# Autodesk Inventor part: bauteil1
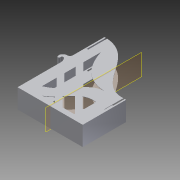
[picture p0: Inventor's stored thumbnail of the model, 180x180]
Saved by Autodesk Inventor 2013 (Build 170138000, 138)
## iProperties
Created: 2012-11
Part Number: bauteil1
Material: Polystyrol
Document SubType Name: Modellieren
Designer: otto
Density: 1.021 g/cm^3
Sheet Metal Width: 0,000 mm
Sheet Metal Length: 0,000 mm
Sheet Metal Area: 0,000 mm^2
Mass: 241.139 g
Surface Area: 2928.45 cm^2
Volume: 236.179 cm^3
Stärke: 3,048 mm
Biegeradius: 3,048 mm
BreiteBiegungsfreistellung: 3,048 mm
TiefeBiegungsfreistellung: 1,524 mm
GrößeEckenfreistellung: 12,192 mm
MinimalRest: 6,096 mm
Übergangsradius: 3,048 mm
JacobiRadiusGröße: 3,048 mm
Abstandsgröße: 3,048 mm
d0: 240,000 mm
d1: 160,000 mm
d2: 320,000 mm
d3: 5,000 mm
d4: 70,000 mm
d5: 5,000 mm
d6: 5,000 mm
d7: 70,000 mm
d8: 5,000 mm
d9: 71,000 mm
d10: 0,00 grd
d11: 238,000 mm
d12: 68,000 mm
d13: 318,000 mm
d14: 0,00 grd
d15: 135,00 grd
d16: 20,000 mm
d17: 20,000 mm
d18: 211,250 mm
d19: 0,00 grd
d38: 71,000 mm
d39: 0,00 grd
d42: 1,500 mm
d43: 1,500 mm
Author: otto
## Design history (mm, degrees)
sketch "Skizze1"
  geometry: L1 (0, 0)-(240, 0); L2 (240, 0)-(240, 160); L3 (0, 0)-(0, 320); L4 (0, 320)-(5, 320); L5 (5, 320)-(5, 250); L6 (5, 250)-(10, 250); L7 (10, 250)-(10, 320); L8 (240, 160)-(235, 160); L9 (235, 160)-(235, 90); L10 (235, 90)-(230, 90); L11 (230, 90)-(230, 160); L12 (193.919, 157.731)-(266.081, 162.269); L13 (139.337, 211.998)-(178.995, 170.807); A1 r 89.613 centre (224.376, 249.437) between (202.259, 162.596) and (257.198, 166.05); 5 further points
  constraints: 26 end point, 6 perpendicular, 4 midpoint, 4 parallel, 1 centre point, 1 horizontal, 1 point on circle, 11 other
  dimensions: "d0" = 240 distance of L1.start L1.end; "d1" = 160 distance of L1.end L2.end; "d2" = 320 distance of L1.start L3.end; "d3" = 5 distance of L3.end L4.end; "d4" = 70 distance of L4.end L5.end; "d5" = 5 distance of L5.end L6.end; "d6" = 5 distance of L2.end L8.end; "d7" = 70 distance of L8.end L9.end; "d8" = 5 distance of L9.end L10.end
extrude "Extrusion1" new body sketch "Skizze1" distance "d9" = 71; taper "d10" = 0 deg
sketch "Skizze2"
  geometry: L1 (1, -1.5)-(239, -1.5); L2 (239, -1.5)-(239, -69.5); L3 (239, -69.5)-(1, -69.5); L4 (1, -69.5)-(1, -1.5); L5 (0, -71)-(240, -71) reference; L6 (0, 0)-(240, 0) reference
  constraints: 8 end point, 2 parallel, 1 horizontal, 1 perpendicular
  dimensions: "d11" = 238 distance of L2.end L3.end; "d12" = 68 distance of L1.end L2.end; "d42" = 1.5 distance between parallel lines of L5 L3; "d43" = 1.5 distance between parallel lines of L6 L1 (derived)
extrude "Extrusion2" cut sketch "Skizze2" distance "d13" = 318; taper "d14" = 0 deg
sketch "Skizze3"
  geometry: L1 (-240, 0)-(-240, 160) reference; L2 (-192.197, 144.809)-(-192.197, 97.685); L3 (-41.305, 48.098)-(-41.305, 8.856); L4 (-72.582, 18.569)-(-192.197, 18.569); L5 (-192.197, 18.569)-(-192.197, 97.685); L6 (-41.678, 48.244)-(-41.678, 265.308); L7 (-41.678, 200.06)-(-120.603, 121.135); L8 (-41.678, 200.06)-(69.939, 200.06); L9 (-120.603, 121.135)-(-107.746, 105.815); L10 (-107.746, 105.815)-(-41.678, 171.883); L11 (-41.678, 130.133)-(-88.876, 82.934); L12 (-88.876, 82.934)-(-74.734, 68.792); L13 (-74.734, 68.792)-(-41.678, 101.849); L14 (-149.245, 90.328)-(-192.197, 47.375); L15 (-133.618, 78.15)-(-192.197, 19.571); L16 (-112.363, 53.394)-(-147.188, 18.569); L17 (-99.087, 38.416)-(-118.934, 18.569); 6 further points
  constraints: 32 end point, 10 parallel, 8 point on line, 3 perpendicular, 1 equal length, 1 horizontal, 22 other
  dimensions: "d15" = 135 deg angle of L7 L8; "d16" = 20 distance of L7.end L9.end; "d17" = 20 distance of L11.end L12.end
extrude "Extrusion3" cut sketch "Skizze3" distance "d18" = 211.25; taper "d19" = 0 deg
sketch "Skizze4"
  geometry: L1 (0, 320)-(0, 0) reference; A1 r 30.238 centre (30.224, 159.082) between (7.575, 179.116) and (0, 160); A2 r 5.422 centre (11.636, 175.524) between (16.987, 174.652) and (7.575, 179.116); A3 r 4.23 centre (21.161, 173.971) between (16.987, 174.652) and (25.005, 172.206); A4 r 14.76 centre (11.592, 178.368) between (25.005, 172.206) and (10.843, 193.109); A5 r 10.381 centre (10.317, 203.477) between (0, 202.323) and (10.843, 193.109)
  constraints: 10 point on circle, 5 centre point, 4 tangent, 1 midpoint, 1 point on line
extrude "Extrusion4" join sketch "Skizze4" distance "d38" = 71; taper "d39" = 0 deg
workplane "Arbeitsebene1"
node "Volumenkörper1"
other parameters: "Stärke" = 3.048 (derived), "KFaktor" = 4.4, "Biegeradius" = 3.048 (= Stärke), "BreiteBiegungsfreistellung" = 3.048 (= Stärke), "TiefeBiegungsfreistellung" = 1.524 (= 0.5 x Stärke), "GrößeEckenfreistellung" = 12.192 (= 4 x Stärke), "AbstandVerbindung" = 0.01, "MinimalRest" = 6.096 (= 2 x Stärke), "Übergangsradius" = 3.048 (= Biegeradius), "JacobiRadiusGröße" = 3.048 (= Stärke), "Abstandsgröße" = 3.048 (= Stärke)
